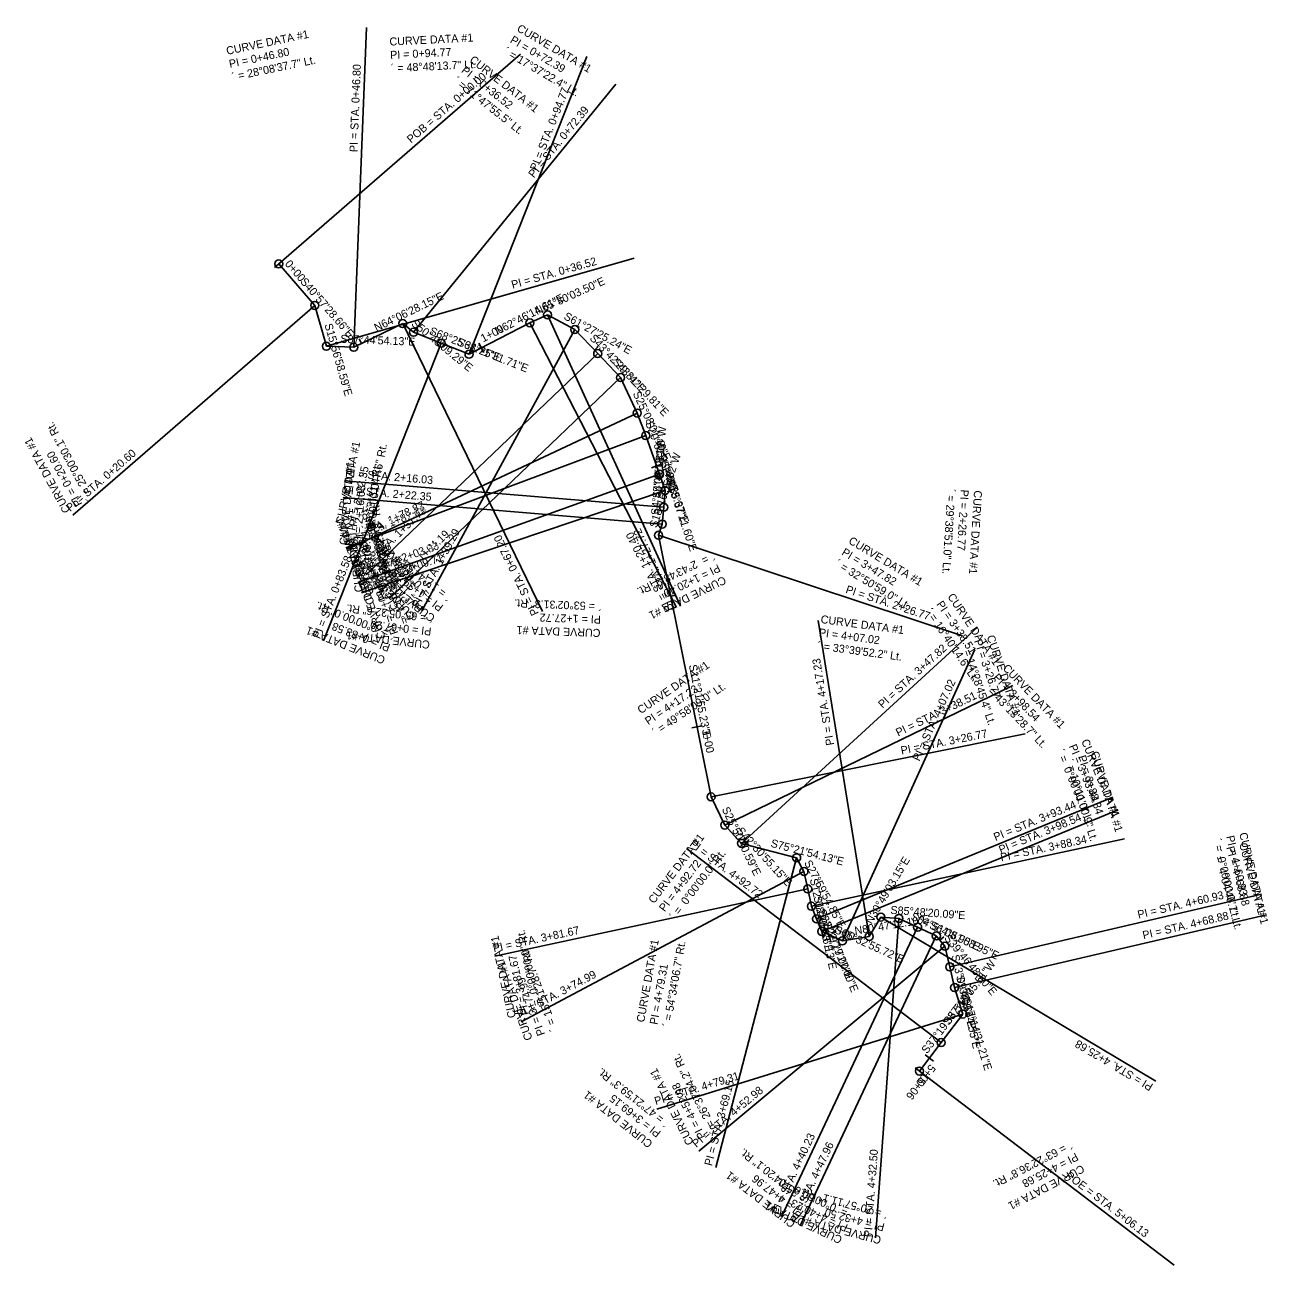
# Model space of a CAD drawing. Extents: x 1158784 to 1165006, y 610007 to 611539.
# Drawn here: x 1161017.3 to 1161483.3, y 610661.9 to 611126.9 of the extents above; entities that cross this region are included whole.
import ezdxf

# ---------------------------------------------------------------- set-up
doc = ezdxf.new("R2010")
doc.units = 0
for name, color, linetype in [('D_Roadway_Centerline', 7, 'Continuous'), ('D_Roadway_Centerline_Bearings', 7, 'Continuous'), ('D_Roadway_Centerline_CurveData', 7, 'Continuous'), ('D_Roadway_Centerline_Flags', 7, 'Continuous'), ('D_Roadway_Centerline_Text', 7, 'Continuous')]:
    doc.layers.add(name, color=color, linetype=linetype)

msp = doc.modelspace()

# ---------------------------------------------------------------- linework, layer by layer
at = {"layer": 'D_Roadway_Centerline'}
for p, q in [((1161112.44, 611037.26), (1161125.94, 611021.71)), ((1161125.94, 611021.71), (1161130.32, 611006.4)), ((1161140.59, 611005.99), (1161158.94, 611014.9)), ((1161158.94, 611014.9), (1161162.97, 611011.62)), ((1161183.77, 611003.39), (1161206.57, 611015.12)), ((1161206.57, 611015.12), (1161213.22, 611018.15)), ((1161213.22, 611018.15), (1161223.39, 611012.62)), ((1161162.97, 611011.62), (1161173.37, 611007.51)), ((1161223.39, 611012.62), (1161231.99, 611003.62)), ((1161130.32, 611006.4), (1161140.59, 611005.99)), ((1161173.37, 611007.51), (1161183.77, 611003.39)), ((1161231.99, 611003.62), (1161240.59, 610994.63)), ((1161240.59, 610994.63), (1161246.83, 610981.34)), ((1161246.83, 610981.34), (1161249.99, 610972.9)), ((1161249.99, 610972.9), (1161255.2, 610958.38)), ((1161255.2, 610958.38), (1161257.25, 610952.31)), ((1161257.25, 610952.31), (1161256.72, 610946.01)), ((1161256.72, 610946.01), (1161256.2, 610939.71)), ((1161256.2, 610939.71), (1161254.81, 610935.52)), ((1161254.81, 610935.52), (1161274.52, 610837.48)), ((1161274.52, 610837.48), (1161279.64, 610826.91)), ((1161279.64, 610826.91), (1161285.93, 610820.05)), ((1161285.93, 610820.05), (1161306.56, 610814.66)), ((1161306.56, 610814.66), (1161309.31, 610809.5)), ((1161309.31, 610809.5), (1161310.71, 610802.98)), ((1161310.71, 610802.98), (1161312.11, 610796.45)), ((1161312.11, 610796.45), (1161314.05, 610791.73)), ((1161314.05, 610791.73), (1161315.99, 610787.01)), ((1161333.78, 610785.14), (1161338.11, 610792.4)), ((1161338.11, 610792.4), (1161344.91, 610791.9)), ((1161344.91, 610791.9), (1161351.91, 610788.61)), ((1161315.99, 610787.01), (1161323.7, 610783.5)), ((1161351.91, 610788.61), (1161358.91, 610785.33)), ((1161323.7, 610783.5), (1161333.78, 610785.14)), ((1161358.91, 610785.33), (1161362.12, 610781.47)), ((1161362.12, 610781.47), (1161363.93, 610773.73)), ((1161363.93, 610773.73), (1161365.74, 610765.98)), ((1161365.74, 610765.98), (1161368.83, 610756.03)), ((1161368.83, 610756.03), (1161360.7, 610745.37)), ((1161360.7, 610745.37), (1161352.57, 610734.7))]:
    msp.add_line(p, q, dxfattribs=at)
at = {"layer": 'D_Roadway_Centerline_Flags'}
for points in [[(1161140.59, 611005.99), (1161145.3, 611125.9)], [(1161112.44, 611037.26), (1161203.06, 611115.92)], [(1161183.77, 611003.39), (1161227.9, 611114.99)], [(1161162.97, 611011.62), (1161238.81, 611104.62)], [(1161130.32, 611006.4), (1161245.7, 611039.37)], [(1161125.94, 611021.71), (1161035.32, 610943.05)], [(1161158.94, 611014.9), (1161211.35, 610906.95)], [(1161206.57, 611015.12), (1161261.47, 610908.42)], [(1161213.22, 611018.15), (1161262.98, 610908.96)], [(1161223.39, 611012.62), (1161166.05, 610907.21)], [(1161173.37, 611007.51), (1161129.24, 610895.91)], [(1161231.99, 611003.62), (1161145.25, 610920.71)], [(1161240.59, 610994.63), (1161153.85, 610911.71)], [(1161246.83, 610981.34), (1161138.19, 610930.37)], [(1161249.99, 610972.9), (1161137.62, 610930.79)], [(1161256.72, 610946.01), (1161137.13, 610955.95)], [(1161255.2, 610958.38), (1161142.25, 610917.85)], [(1161256.2, 610939.71), (1161136.61, 610949.65)], [(1161257.25, 610952.31), (1161143.53, 610913.99)], [(1161254.81, 610935.52), (1161368.75, 610897.87)], [(1161333.78, 610785.14), (1161314.57, 610903.59)], [(1161285.93, 610820.05), (1161374.38, 610901.14)], [(1161323.7, 610783.5), (1161373.37, 610892.74)], [(1161279.64, 610826.91), (1161387.64, 610879.22)], [(1161274.52, 610837.48), (1161392.16, 610861.12)], [(1161314.05, 610791.73), (1161425.06, 610837.31)], [(1161315.99, 610787.01), (1161427, 610832.59)], [(1161312.11, 610796.45), (1161429.43, 610821.68)], [(1161360.7, 610745.37), (1161265.27, 610818.13)], [(1161306.56, 610814.66), (1161276.25, 610698.55)], [(1161309.31, 610809.5), (1161203.35, 610753.17)], [(1161310.71, 610802.98), (1161193.39, 610777.74)], [(1161363.93, 610773.73), (1161480.78, 610801.05)], [(1161344.91, 610791.9), (1161336.13, 610672.22)], [(1161338.11, 610792.4), (1161441.17, 610730.92)], [(1161365.74, 610765.98), (1161482.59, 610793.31)], [(1161351.91, 610788.61), (1161300.92, 610679.99)], [(1161362.12, 610781.47), (1161269.9, 610704.69)], [(1161358.91, 610785.33), (1161307.92, 610676.7)], [(1161368.83, 610756.03), (1161254.22, 610720.46)], [(1161352.57, 610734.7), (1161447.99, 610661.94)]]:
    msp.add_lwpolyline(points, dxfattribs=at)
for centre in [(1161112.44, 611037.26), (1161125.94, 611021.71), (1161213.22, 611018.15), (1161158.94, 611014.9), (1161206.57, 611015.12), (1161162.97, 611011.62), (1161223.39, 611012.62), (1161130.32, 611006.4), (1161140.59, 611005.99), (1161173.37, 611007.51), (1161231.99, 611003.62), (1161183.77, 611003.39), (1161240.59, 610994.63), (1161246.83, 610981.34), (1161249.99, 610972.9), (1161255.2, 610958.38), (1161257.25, 610952.31), (1161256.72, 610946.01), (1161256.2, 610939.71), (1161254.81, 610935.52), (1161274.52, 610837.48), (1161279.64, 610826.91), (1161285.93, 610820.05), (1161306.56, 610814.66), (1161309.31, 610809.5), (1161310.71, 610802.98), (1161312.11, 610796.45), (1161314.05, 610791.73), (1161338.11, 610792.4), (1161344.91, 610791.9), (1161315.99, 610787.01), (1161333.78, 610785.14), (1161351.91, 610788.61), (1161358.91, 610785.33), (1161323.7, 610783.5), (1161362.12, 610781.47), (1161363.93, 610773.73), (1161365.74, 610765.98), (1161368.83, 610756.03), (1161360.7, 610745.37), (1161352.57, 610734.7)]:
    msp.add_circle(centre, 1.5, dxfattribs=at)
at = {"layer": 'D_Roadway_Centerline_Text'}
for points in [[(1161113.95, 611038.57), (1161110.93, 611035.95)], [(1161142.59, 611009.19), (1161143.47, 611007.39)], [(1161187.51, 611007.56), (1161189.34, 611004.01)], [(1161232.23, 611006.26), (1161230.79, 611004.88)], [(1161255.97, 610962.16), (1161252.2, 610960.81)], [(1161261.35, 610913.13), (1161259.39, 610912.74)], [(1161271.2, 610864.11), (1161267.28, 610863.33)], [(1161288.54, 610821.43), (1161288.04, 610819.5)], [(1161318.14, 610788.23), (1161316.49, 610784.59)], [(1161361.75, 610785.04), (1161360.21, 610783.76)], [(1161357.87, 610738.36), (1161354.69, 610740.79)], [(1161354.16, 610733.49), (1161350.98, 610735.91)], [(1161354.16, 610733.49), (1161350.98, 610735.91)]]:
    msp.add_lwpolyline(points, dxfattribs=at)

# ---------------------------------------------------------------- texts
at = {"layer": 'D_Roadway_Centerline_Bearings'}
for s, rotation, p in [('S40%%d57\'28.66"E', 310.958, (1161120.32, 611030.47)), ('N65%%d30\'03.50"E', 24.499, (1161209.27, 611018)), ('N64%%d06\'28.15"E', 25.8922, (1161149.11, 611011.8)), ('N62%%d46\'14.61"E', 27.2293, (1161194.48, 611010.59)), ('S15%%d56\'58.59"E', 285.9496, (1161129.57, 611014.46)), ('S50%%d48\'09.29"E', 320.8026, (1161161.9, 611014.42)), ('S61%%d27\'25.24"E', 331.457, (1161219.02, 611016.71)), ('S87%%d44\'54.13"E', 357.7484, (1161135.51, 611007.69)), ('S68%%d25\'31.71"E', 338.4255, (1161168.72, 611010.96)), ('S43%%d42\'29.81"E', 313.7083, (1161228.77, 611009.16)), ('S68%%d25\'31.71"E', 338.4255, (1161179.12, 611006.84)), ('S43%%d42\'29.81"E', 313.7083, (1161237.38, 611000.16)), ('S25%%d08\'01.10"E', 295.1336, (1161245.07, 610988.62)), ('S20%%d32\'25.45"E', 290.5404, (1161249.81, 610977.64)), ('S4%%d45\'08.18"W', 85.2477, (1161255.49, 610949.28)), ('S4%%d45\'08.18"W', 85.2477, (1161254.97, 610942.99)), ('S18%%d16\'55.82"W', 71.7178, (1161254.08, 610938.08)), ('S19%%d44\'35.67"E', 289.7432, (1161254.01, 610966.15)), ('S18%%d37\'21.60"E', 288.6227, (1161257.64, 610955.83)), ('S11%%d21\'55.23"E', 281.3653, (1161266.14, 610886.79)), ('S25%%d50\'40.59"E', 295.8446, (1161278.43, 610832.85)), ('S42%%d30\'55.15"E', 312.5153, (1161283.89, 610824.49)), ('S75%%d21\'54.13"E', 345.365, (1161296.62, 610818.8)), ('N30%%d49\'03.15"E', 59.1825, (1161334.66, 610789.54)), ('S27%%d59\'54.85"E', 297.9986, (1161309.26, 610812.79)), ('S12%%d08\'26.13"E', 282.1406, (1161311.47, 610806.55)), ('S12%%d08\'26.13"E', 282.1406, (1161312.88, 610800.03)), ('S85%%d48\'20.09"E', 355.8056, (1161341.62, 610793.64)), ('S22%%d19\'27.00"E', 292.3242, (1161314.47, 610794.66)), ('N80%%d47\'12.10"E', 9.2133, (1161328.5, 610785.8)), ('S64%%d51\'08.95"E', 334.8525, (1161349.05, 610791.61)), ('S22%%d19\'27.00"E', 292.3242, (1161316.41, 610789.94)), ('S65%%d32\'55.72"E', 335.5488, (1161320.47, 610786.62)), ('S64%%d51\'08.95"E', 334.8525, (1161356.05, 610788.33)), ('S39%%d46\'48.80"E', 309.7802, (1161361.67, 610784.36)), ('S13%%d09\'44.55"E', 283.1624, (1161364.48, 610777.94)), ('S37%%d19\'35.51"W', 52.6735, (1161363.57, 610751.61)), ('S13%%d09\'44.55"E', 283.1624, (1161366.3, 610770.2)), ('S37%%d19\'35.51"W', 52.6735, (1161355.44, 610740.94)), ('S17%%d14\'31.21"E', 287.242, (1161368.72, 610761.45))]:
    msp.add_text(s, height=3, rotation=rotation, dxfattribs=at).set_placement(p)
at = {"layer": 'D_Roadway_Centerline_CurveData'}
for s, rotation, p in [('CURVE DATA #1', 329.614, (1161201.44, 611124.69)), ('CURVE DATA #1', 11.8203, (1161093.13, 611115.59)), ('CURVE DATA #1', 2.8274, (1161154.03, 611119.07)), ('PI = 0+72.39', 329.614, (1161198.91, 611120.38)), ('PI = 0+46.80', 11.8203, (1161094.16, 611110.7)), ('PI = 0+94.77', 2.8274, (1161154.28, 611114.07)), ('´ = 17%%d37\'22.4" Lt.', 329.614, (1161196.39, 611116.06)), ('´ = 28%%d08\'37.7" Lt.', 11.8203, (1161095.18, 611105.81)), ('´ = 48%%d48\'13.7" Lt.', 2.8274, (1161154.53, 611109.08)), ('CURVE DATA #1', 321.849, (1161183.72, 611113.23)), ('PI = 0+36.52', 321.849, (1161180.63, 611109.3)), ('´ = 71%%d47\'55.5" Lt.', 321.849, (1161177.54, 611105.36)), ('´ = 25%%d00\'30.1" Rt.', 118.4538, (1161043.3, 610949.63)), ('CURVE DATA #1', 118.4538, (1161034.51, 610944.86)), ('CURVE DATA #1', 78.4828, (1161136.76, 610939.56)), ('´ = 13%%d31\'47.6" Rt.', 78.4828, (1161146.56, 610937.56)), ('PI = 0+20.60', 118.4538, (1161038.91, 610947.25)), ('CURVE DATA #1', 85.2477, (1161138.14, 610931.79)), ('PI = 2+22.35', 78.4828, (1161141.66, 610938.56)), ('´ =  0%%d00\'00.0" Rt.', 85.2477, (1161148.1, 610930.96)), ('PI = 2+16.03', 85.2477, (1161143.12, 610931.37)), ('´ = 29%%d38\'51.0" Lt.', 266.5416, (1161363.06, 610953.02)), ('PI = 2+26.77', 266.5416, (1161368.06, 610952.72)), ('CURVE DATA #1', 266.5416, (1161373.05, 610952.41)), ('CURVE DATA #1', 96.9352, (1161144, 610914.36)), ('´ =  4%%d35\'35.6" Rt.', 112.837, (1161157.53, 610917.69)), ('´ = 23%%d22\'29.8" Rt.', 96.9352, (1161153.93, 610915.57)), ('CURVE DATA #1', 112.837, (1161148.31, 610913.81)), ('´ =  0%%d47\'49.8" Rt.', 110.1418, (1161157.8, 610913.52)), ('´ = 18%%d34\'28.7" Rt.', 124.421, (1161165.89, 610914.34)), ('CURVE DATA #1', 110.1418, (1161148.41, 610910.08)), ('PI = 1+78.87', 112.837, (1161152.92, 610915.75)), ('PI = 2+09.71', 96.9352, (1161148.96, 610914.96)), ('CURVE DATA #1', 124.421, (1161157.65, 610908.69)), ('PI = 1+87.88', 110.1418, (1161153.1, 610911.8)), ('´ =  0%%d00\'00.0" Rt.', 133.7083, (1161171.23, 610912.34)), ('´ = 17%%d44\'55.4" Rt.', 142.5826, (1161177.44, 610913.06)), ('PI = 3+47.82', 328.9402, (1161323.15, 610928.37)), ('CURVE DATA #1', 328.9402, (1161325.73, 610932.66)), ('CURVE DATA #1', 109.183, (1161152.58, 610897.27)), ('CURVE DATA #1', 133.7083, (1161164, 610905.43)), ('PI = 1+64.19', 124.421, (1161161.77, 610911.52)), ('´ =  1%%d07\'14.1" Rt.', 109.183, (1161162.03, 610900.56)), ('´ =  2%%d43\'48.9" Rt.', 205.8642, (1161274.84, 610929.31)), ('´ = 32%%d50\'59.0" Lt.', 328.9402, (1161320.57, 610924.09)), ('CURVE DATA #1', 142.5826, (1161171.36, 610905.12)), ('PI = 1+51.74', 133.7083, (1161167.61, 610908.89)), ('PI = 1+39.29', 142.5826, (1161174.4, 610909.09)), ('PI = 1+20.40', 205.8642, (1161277.02, 610924.81)), ('PI = 2+03.30', 109.183, (1161157.3, 610898.92)), ('CURVE DATA #1', 205.8642, (1161279.2, 610920.31)), ('CURVE DATA #1', 304.18, (1161362.95, 610912.49)), ('´ =  0%%d00\'00.0" Rt.', 158.4255, (1161156.34, 610899.18)), ('´ = 65%%d05\'22.6" Rt.', 173.3474, (1161170.39, 610905.84)), ('´ = 53%%d02\'31.3" Rt.', 177.978, (1161233.43, 610910.37)), ('´ = 16%%d40\'14.6" Lt.', 304.18, (1161354.67, 610906.87)), ('PI = 3+38.51', 304.18, (1161358.81, 610909.68)), ('PI = 0+83.58', 158.4255, (1161154.5, 610894.53)), ('PI = 0+67.20', 173.3474, (1161169.81, 610900.87)), ('PI = 1+27.72', 177.978, (1161233.25, 610905.38)), ('CURVE DATA #1', 352.3811, (1161315.43, 610902.65)), ('CURVE DATA #1', 158.4255, (1161152.67, 610889.88)), ('CURVE DATA #1', 173.3474, (1161169.23, 610895.91)), ('CURVE DATA #1', 177.978, (1161233.08, 610900.38)), ('PI = 4+07.02', 352.3811, (1161314.76, 610897.7)), ('CURVE DATA #1', 288.605, (1161377.75, 610897.55)), ('´ = 33%%d39\'52.2" Lt.', 352.3811, (1161314.1, 610892.74)), ('´ = 14%%d28\'45.4" Lt.', 288.605, (1161368.27, 610894.36)), ('PI = 3+26.77', 288.605, (1161373.01, 610895.96)), ('CURVE DATA #1', 34.1979, (1161248.17, 610868.42)), ('CURVE DATA #1', 313.9365, (1161383.59, 610885.47)), ('PI = 4+17.23', 34.1979, (1161250.98, 610864.28)), ('´ = 49%%d58\'09.0" Lt.', 34.1979, (1161253.79, 610860.15)), ('´ = 43%%d13\'28.7" Lt.', 313.9365, (1161376.39, 610878.54)), ('PI = 3+98.54', 313.9365, (1161379.99, 610882)), ('PI = 3+93.44', 292.3242, (1161408.54, 610856.47)), ('CURVE DATA #1', 292.3242, (1161413.17, 610858.37)), ('´ =  0%%d00\'00.0" Lt.', 292.3242, (1161403.92, 610854.57)), ('´ = 10%%d11\'00.9" Lt.', 287.2324, (1161407.2, 610851.07)), ('PI = 3+88.34', 287.2324, (1161411.98, 610852.55)), ('CURVE DATA #1', 287.2324, (1161416.75, 610854.03)), ('CURVE DATA #1', 283.1624, (1161472.39, 610823.74)), ('CURVE DATA #1', 52.6735, (1161253.11, 610797.23)), ('´ =  0%%d00\'00.0" Lt.', 283.1624, (1161462.65, 610821.46)), ('PI = 4+60.93', 283.1624, (1161467.52, 610822.6)), ('PI = 4+68.88', 285.2022, (1161467.53, 610818.51)), ('CURVE DATA #1', 285.2022, (1161472.35, 610819.83)), ('´ =  0%%d00\'00.0" Rt.', 52.6735, (1161261.06, 610791.16)), ('´ =  4%%d04\'46.7" Lt.', 285.2022, (1161462.7, 610817.2)), ('PI = 4+92.72', 52.6735, (1161257.08, 610794.19)), ('´ =  0%%d00\'00.0" Rt.', 102.1406, (1161211.15, 610757.01)), ('CURVE DATA #1', 102.1406, (1161201.37, 610754.91)), ('CURVE DATA #1', 79.9577, (1161249.44, 610752.8)), ('´ = 54%%d34\'06.7" Rt.', 79.9577, (1161259.28, 610751.06)), ('PI = 3+81.67', 102.1406, (1161206.26, 610755.96)), ('´ = 15%%d51\'28.7" Rt.', 110.0696, (1161217.04, 610750.24)), ('CURVE DATA #1', 110.0696, (1161207.65, 610746.81)), ('PI = 4+79.31', 79.9577, (1161254.36, 610751.93)), ('PI = 3+74.99', 110.0696, (1161212.34, 610748.53)), ('´ = 26%%d37\'04.2" Rt.', 116.4713, (1161277.03, 610712.29)), ('´ = 47%%d21\'59.3" Rt.', 141.6818, (1161259.05, 610715.83)), ('CURVE DATA #1', 116.4713, (1161268.08, 610707.84)), ('PI = 4+52.98', 116.4713, (1161272.56, 610710.06)), ('CURVE DATA #1', 141.6818, (1161252.85, 610707.98)), ('PI = 3+69.15', 141.6818, (1161255.95, 610711.91)), ('´ = 25%%d04\'20.1" Rt.', 142.3164, (1161312.5, 610685.97)), ('´ = 63%%d22\'36.8" Rt.', 207.494, (1161408.8, 610708.56)), ('PI = 4+25.68', 207.494, (1161411.11, 610704.13)), ('CURVE DATA #1', 207.494, (1161413.42, 610699.69)), ('CURVE DATA #1', 142.3164, (1161306.38, 610678.06)), ('PI = 4+47.96', 142.3164, (1161309.44, 610682.02)), ('´ =  0%%d00\'00.0" Rt.', 154.8525, (1161328.17, 610681.55)), ('´ = 20%%d57\'11.1" Rt.', 165.329, (1161341.03, 610682.31)), ('CURVE DATA #1', 154.8525, (1161323.92, 610672.5)), ('PI = 4+40.23', 154.8525, (1161326.04, 610677.03)), ('CURVE DATA #1', 165.329, (1161338.5, 610672.63)), ('PI = 4+32.50', 165.329, (1161339.76, 610677.47))]:
    msp.add_text(s, height=3, rotation=rotation, dxfattribs=at).set_placement(p)
at = {"layer": 'D_Roadway_Centerline_Flags'}
for s, rotation, p in [('PI = STA. 0+46.80', 87.7484, (1161141.96, 611079.09)), ('POB = STA. 0+00.00', 40.958, (1161162.07, 611082.33)), ('PI = STA. 0+94.77', 68.4255, (1161209.26, 611071.92)), ('PI = STA. 0+72.39', 50.8026, (1161208.04, 611069.27)), ('PI = STA. 0+36.52', 15.9496, (1161200.13, 611027.91)), ('PI = STA. 0+20.60', 40.958, (1161034.34, 610944.18)), ('PI = STA. 2+16.03', 355.2477, (1161137.26, 610957.45)), ('PI = STA. 2+22.35', 355.2477, (1161136.73, 610951.15)), ('PI = STA. 1+87.88', 20.5404, (1161137.09, 610932.2)), ('PI = STA. 1+78.87', 25.1336, (1161137.55, 610931.73)), ('PI = STA. 1+51.74', 43.7083, (1161144.21, 610921.79)), ('PI = STA. 1+64.19', 43.7083, (1161152.81, 610912.79)), ('PI = STA. 1+39.29', 61.457, (1161164.73, 610907.93)), ('PI = STA. 0+67.20', 115.8922, (1161210, 610906.29)), ('PI = STA. 1+20.40', 117.2293, (1161260.14, 610907.73)), ('PI = STA. 1+27.72', 114.499, (1161261.62, 610908.34)), ('PI = STA. 2+03.30', 19.7432, (1161141.75, 610919.26)), ('PI = STA. 0+83.58', 68.4255, (1161127.85, 610896.47)), ('PI = STA. 2+09.71', 18.6227, (1161143.05, 610915.41)), ('PI = STA. 2+26.77', 341.7178, (1161324.69, 610914.01)), ('PI = STA. 3+47.82', 42.5153, (1161338.75, 610870.51)), ('PI = STA. 4+17.23', 99.2133, (1161320.61, 610856.99)), ('PI = STA. 4+07.02', 65.5488, (1161352.57, 610850.61)), ('PI = STA. 3+38.51', 25.8446, (1161344.6, 610860.04)), ('PI = STA. 3+26.77', 11.3653, (1161345.89, 610853.35)), ('PI = STA. 3+93.44', 22.3242, (1161381.1, 610820.88)), ('PI = STA. 3+98.54', 22.3242, (1161383.04, 610816.16)), ('PI = STA. 4+92.72', 322.6735, (1161266.18, 610819.32)), ('PI = STA. 3+88.34', 12.1406, (1161383.26, 610813.29)), ('PI = STA. 4+60.93', 13.1624, (1161434.7, 610791.82)), ('PI = STA. 4+68.88', 13.1624, (1161436.58, 610784.09)), ('PI = STA. 3+81.67', 12.1406, (1161193.08, 610779.2)), ('PI = STA. 3+74.99', 27.9986, (1161202.65, 610754.49)), ('PI = STA. 4+25.68', 149.1825, (1161440.4, 610729.63)), ('PI = STA. 4+79.31', 17.242, (1161253.78, 610721.89)), ('PI = STA. 3+69.15', 75.365, (1161274.79, 610698.93)), ('PI = STA. 4+52.98', 39.7802, (1161268.94, 610705.84)), ('PI = STA. 4+40.23', 64.8525, (1161299.56, 610680.62)), ('PI = STA. 4+47.96', 64.8525, (1161306.56, 610677.34)), ('PI = STA. 4+32.50', 85.8056, (1161334.64, 610672.33)), ('POE = STA. 5+06.13', 322.6735, (1161407.11, 610695))]:
    msp.add_text(s, height=3, rotation=rotation, dxfattribs=at).set_placement(p)
at = {"layer": 'D_Roadway_Centerline_Text'}
for s, rotation, p in [('0+00', 310.958, (1161114.56, 611037.11)), ('1+00', 27.2293, (1161189.07, 611007.81)), ('2+00', 289.7432, (1161256, 610960.58)), ('3+00', 281.3653, (1161271.01, 610862.55)), ('4+00', 335.5488, (1161319.3, 610787.15)), ('5+00', 232.6735, (1161356.56, 610737.47)), ('5+06', 232.6735, (1161352.85, 610732.6)), ('5+06', 232.6735, (1161352.85, 610732.6))]:
    msp.add_text(s, height=3, rotation=rotation, dxfattribs=at).set_placement(p)

doc.saveas('drawing.dxf')
